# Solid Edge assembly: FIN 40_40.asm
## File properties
Title: Zylinder
Author: bmolnar
Template: iso assembly.asm
Last saved by: bmolnar
Revision: 13
Application: Solid Edge
Username: bmolnar
Dokumentum tartalom típus: 1
Document Number: FIN 40/40
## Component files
Kit_1.par
Profilrohr.par
Kit_2.par
Kolbenstange.par
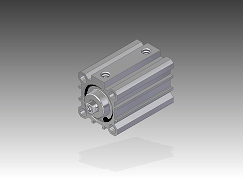
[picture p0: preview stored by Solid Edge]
